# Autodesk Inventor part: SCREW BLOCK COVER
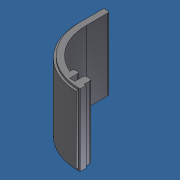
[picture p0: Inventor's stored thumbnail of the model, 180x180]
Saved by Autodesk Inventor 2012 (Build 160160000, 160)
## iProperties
Created: 2015-03
Part Number: SCREW BLOCK COVER
Material: ABS Plastic
Document SubType Name: Modeling
Designer: Admin
Density: 1.06 g/cm^3
Mass: 1.11883 g
Surface Area: 13.1814 cm^2
Volume: 1.0555 cm^3
Author: Admin
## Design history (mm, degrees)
feature "Base1"
body "Solid1"
